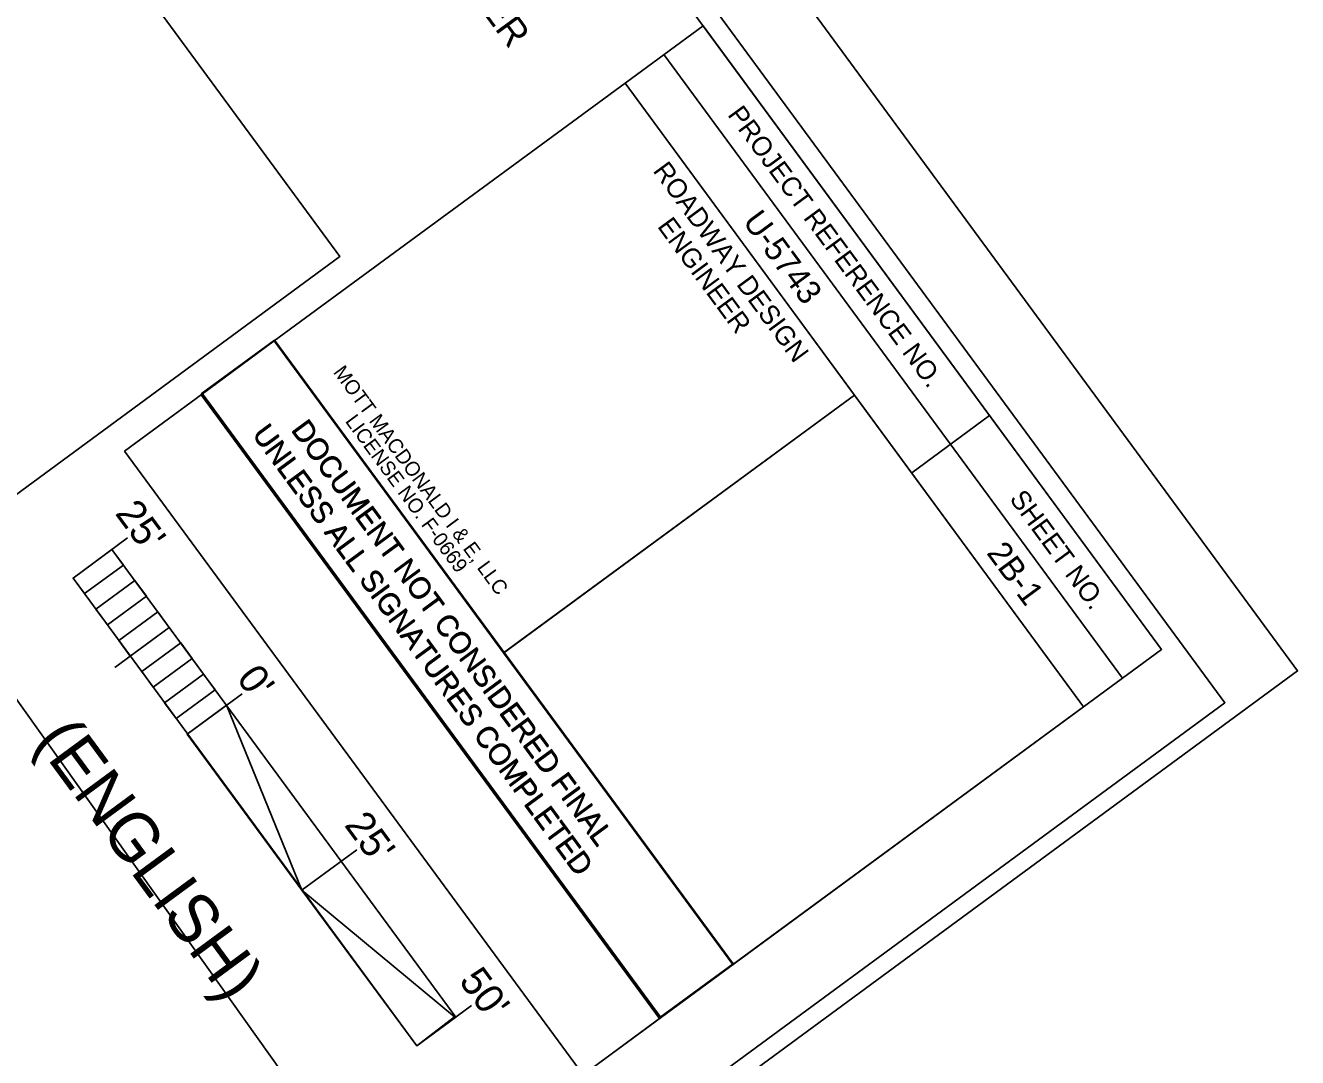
# Model space of a CAD drawing. Extents: x 1763480 to 1764420, y 711010 to 712012.
# Drawn here: x 1764255.2 to 1764419.6, y 711284 to 711417.4 of the extents above; entities that cross this region are included whole.
import ezdxf

# ---------------------------------------------------------------- set-up
doc = ezdxf.new("R2010")
doc.units = 0
for name, color, linetype in [('Old_Level_40', 7, 'Continuous'), ('Old_Level_42', 7, 'Continuous'), ('P-WATER', 7, 'Continuous'), ('Prop DSN Text', 7, 'Continuous'), ('Prop Horizontal Alignment Station Label', 7, 'Continuous'), ('Prop PHM English Scale CELL', 7, 'Continuous'), ('Sheet Clip Boundary CELL', 7, 'Continuous'), ('Sheet Data Field CELL', 7, 'Continuous'), ('Sheet Plot Border Inside CELL', 7, 'Continuous'), ('Sheet Plot Border Outside CELL', 7, 'Continuous')]:
    doc.layers.add(name, color=color, linetype=linetype)

msp = doc.modelspace()

# ---------------------------------------------------------------- linework, layer by layer
at = {"layer": 'Old_Level_40'}
msp.add_lwpolyline([(1764268.03, 711362.41), (1764327.28, 711281.82), (1764337.34, 711289.22), (1764278.09, 711369.81)], close=True, dxfattribs=at)
at = {"layer": 'Old_Level_42'}
msp.add_line((1764337.34, 711289.22), (1764278.09, 711369.81), dxfattribs=at)
at = {"layer": 'P-WATER'}
for p, q in [((1764337.73, 711413.66), (1764396.98, 711333.07)), ((1764362.33, 711369.65), (1764317.03, 711336.35)), ((1764379.81, 711366.99), (1764369.74, 711359.58))]:
    msp.add_line(p, q, dxfattribs=at)
for points in [[(1764402.04, 711336.79), (1763957.77, 711941.04), (1763535.55, 711630.61), (1763979.82, 711026.35)], [(1764342.79, 711417.38), (1764402.04, 711336.79), (1764391.95, 711329.37), (1764332.7, 711409.96)], [(1764332.7, 711409.96), (1764362.33, 711369.65), (1764317.01, 711336.33), (1764287.38, 711376.64)], [(1764362.33, 711369.65), (1764391.95, 711329.37), (1764346.63, 711296.05), (1764317.01, 711336.33)]]:
    msp.add_lwpolyline(points, close=True, dxfattribs=at)
at = {"layer": 'Prop Horizontal Alignment Station Label'}
msp.add_lwpolyline([(1763957.77, 711941.04), (1764052.94, 711811.6), (1764008.24, 711778.74), (1764295.85, 711387.56), (1764241.65, 711347.71), (1764301.88, 711263.14), (1763979.82, 711026.35), (1763792.92, 711280.55), (1763982.56, 711419.98), (1763871.46, 711571.1), (1763681.82, 711431.66), (1763535.55, 711630.61)], close=True, dxfattribs=at)
at = {"layer": 'Prop PHM English Scale CELL'}
for p, q in [((1764268.42, 711351.19), (1764261.37, 711346)), ((1764268.82, 711351.48), (1764268.82, 711351.48)), ((1764266.4, 711349.7), (1764261.37, 711346)), ((1764310.83, 711289.28), (1764266.4, 711349.7)), ((1764261.37, 711346), (1764305.79, 711285.58)), ((1764273.81, 711339.63), (1764266.76, 711334.45)), ((1764283.23, 711331.04), (1764276.14, 711325.83)), ((1764298.03, 711310.9), (1764290.99, 711305.72)), ((1764298.44, 711311.2), (1764298.44, 711311.2)), ((1764312.84, 711290.76), (1764305.79, 711285.58)), ((1764313.25, 711291.06), (1764313.25, 711291.06)), ((1764305.79, 711285.58), (1764310.83, 711289.28))]:
    msp.add_line(p, q, dxfattribs=at)
for points in [[(1764267.88, 711347.69), (1764266.4, 711349.7), (1764261.37, 711346), (1764262.85, 711343.99)], [(1764269.36, 711345.68), (1764270.85, 711343.66), (1764265.81, 711339.96), (1764264.33, 711341.97)], [(1764272.33, 711341.65), (1764273.81, 711339.63), (1764268.77, 711335.93), (1764267.29, 711337.95)], [(1764275.29, 711337.62), (1764276.77, 711335.6), (1764271.73, 711331.9), (1764270.25, 711333.92)], [(1764278.25, 711333.59), (1764279.73, 711331.58), (1764274.7, 711327.87), (1764273.21, 711329.89)], [(1764281.21, 711329.56), (1764290.95, 711305.69), (1764276.14, 711325.83)], [(1764290.95, 711305.69), (1764310.68, 711289.32), (1764305.79, 711285.58)]]:
    msp.add_lwpolyline(points, close=True, dxfattribs=at)
at = {"layer": 'Sheet Clip Boundary CELL'}
for p, q in [((1764277.91, 711369.68), (1764287.38, 711376.64)), ((1764277.94, 711369.8), (1764287.41, 711376.76)), ((1764287.38, 711376.64), (1764346.63, 711296.05)), ((1764287.41, 711376.76), (1764346.66, 711296.17)), ((1764337.16, 711289.09), (1764277.91, 711369.68)), ((1764337.19, 711289.21), (1764277.94, 711369.8)), ((1764346.65, 711296.17), (1764337.19, 711289.21)), ((1764346.62, 711296.05), (1764337.16, 711289.09))]:
    msp.add_line(p, q, dxfattribs=at)
at = {"layer": 'Sheet Plot Border Inside CELL'}
msp.add_lwpolyline([(1763491.78, 711688.55), (1763985.22, 711017.43), (1764410.21, 711329.9), (1763916.77, 712001.02)], close=True, dxfattribs=at)
at = {"layer": 'Sheet Plot Border Outside CELL'}
msp.add_lwpolyline([(1763479.87, 711687.86), (1763978.5, 711009.69), (1764419.6, 711334.01), (1763920.98, 712012.18)], close=True, dxfattribs=at)

# ---------------------------------------------------------------- texts
at = {"layer": 'P-WATER'}
for s, p in [('PROJECT REFERENCE NO.', (1764345.86, 711405.86)), ('ROADWAY DESIGN', (1764336.22, 711398.62)), ('ENGINEER', (1764336.79, 711391.44)), ('SHEET NO.', (1764382.29, 711356.22))]:
    msp.add_text(s, height=2.5, rotation=306.325, dxfattribs=at).set_placement(p)
at = {"layer": 'Prop DSN Text'}
for s, height, rotation, p in [('PAVED SHOULDER', 3.5, 306.2176, (1764292.29, 711449.1)), ('MOTT MACDONALD I & E, LLC', 1.875, 306.325, (1764294.92, 711372.59)), (' LICENSE NO. F-0669', 1.875, 306.325, (1764296.05, 711366.83))]:
    msp.add_text(s, height=height, rotation=rotation, dxfattribs=at).set_placement(p)
at = {"layer": 'Prop PHM English Scale CELL'}
for s, height, p in [("25'", 3.75, (1764266.71, 711354.35)), ("0'", 3.75, (1764282.4, 711333.02)), ('(ENGLISH)', 6.25, (1764256.3, 711324.95)), ("25'", 3.75, (1764296.33, 711314.07)), ("50'", 3.75, (1764311.14, 711293.92))]:
    msp.add_text(s, height=height, rotation=306.325, dxfattribs=at).set_placement(p)
at = {"layer": 'Sheet Clip Boundary CELL'}
for s, p in [('UNLESS ALL SIGNATURES COMPLETED', (1764284.41, 711364.52)), ('UNLESS ALL SIGNATURES COMPLETED', (1764284.44, 711364.64)), ('DOCUMENT NOT CONSIDERED FINAL', (1764289.45, 711365.08)), ('DOCUMENT NOT CONSIDERED FINAL', (1764289.48, 711365.2))]:
    msp.add_text(s, height=2.75, rotation=306.325, dxfattribs=at).set_placement(p)
at = {"layer": 'Sheet Data Field CELL'}
for s, p in [('U-5743', (1764347.81, 711392.06)), ('2B-1', (1764379.33, 711349.24))]:
    msp.add_text(s, height=3.1, rotation=306.325, dxfattribs=at).set_placement(p)

doc.saveas('drawing.dxf')
